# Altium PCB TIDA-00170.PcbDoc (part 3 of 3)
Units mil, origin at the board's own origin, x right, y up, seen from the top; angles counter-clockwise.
Board outline 3780 x 2000 mil, 4 copper layers (Top Layer, L2_GND-PLANE, L3_PWR-PLANE, Bottom Layer), stack 90 mil thick; 275 components, 132 nets, 768 pads, 262 vias.
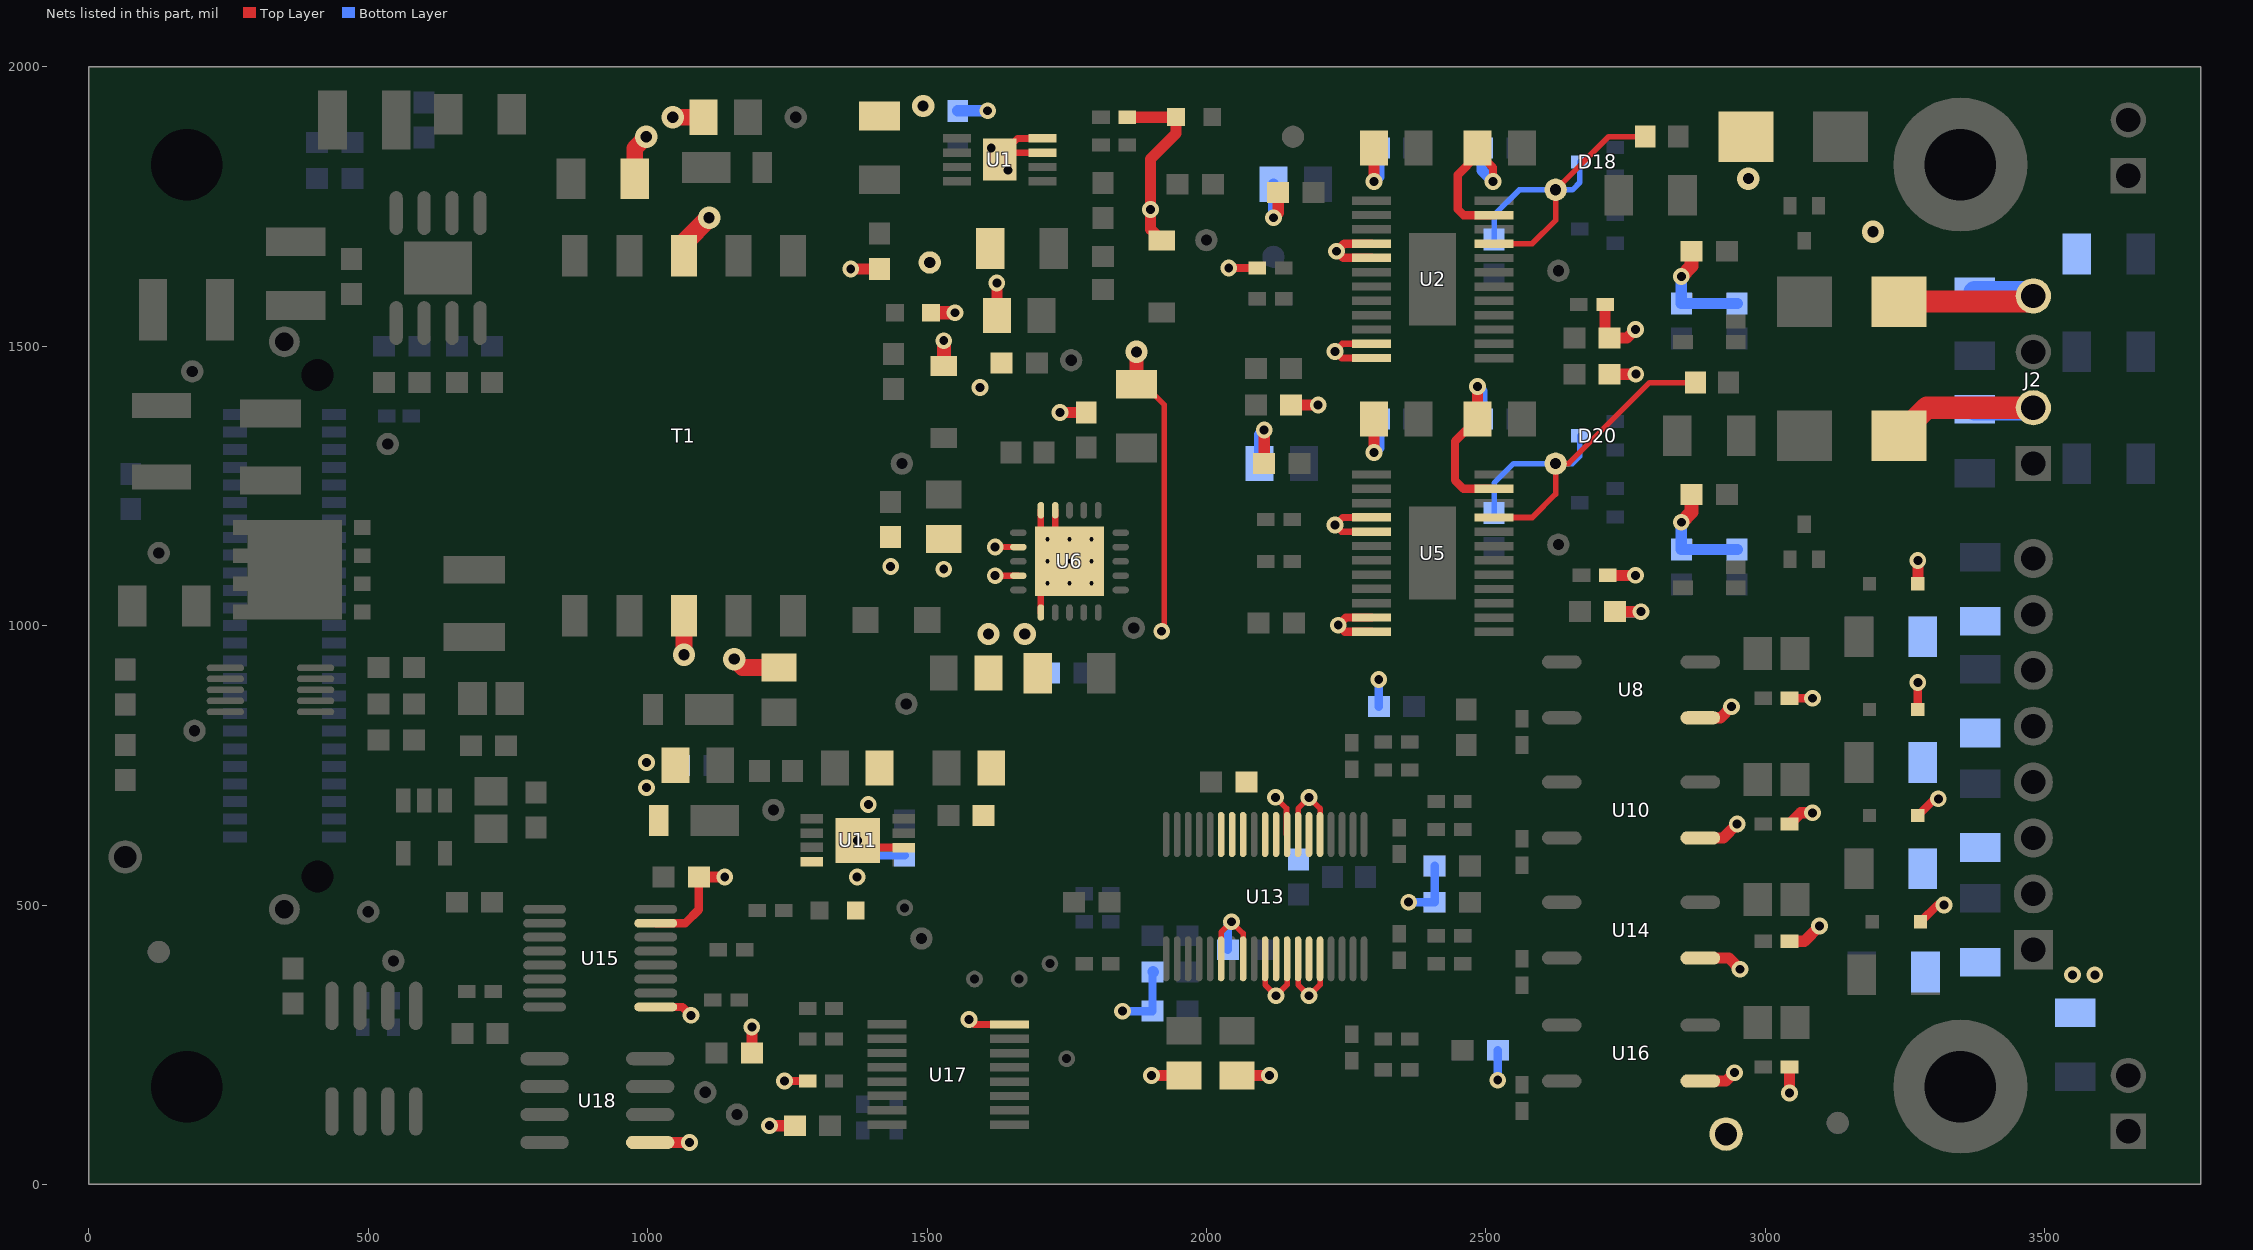
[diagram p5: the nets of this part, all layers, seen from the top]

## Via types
v1: diameter 30, hole 16, Top Layer to Bottom Layer, tented both sides, 197 vias
v2: diameter 40, hole 20, Top Layer to Bottom Layer, tented both sides, 46 vias
v3: diameter 20, hole 8, Top Layer to Bottom Layer, tented both sides, 9 vias
v4: diameter 24, hole 12, Top Layer to Bottom Layer, tented both sides, 6 vias
v5: diameter 25.98, hole 12, Top Layer to Bottom Layer, tented both sides, 4 vias

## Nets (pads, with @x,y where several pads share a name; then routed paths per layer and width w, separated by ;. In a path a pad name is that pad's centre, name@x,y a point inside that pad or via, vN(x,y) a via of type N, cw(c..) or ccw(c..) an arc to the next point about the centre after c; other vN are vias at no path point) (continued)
SGND: C3.1 C4.2 C5.2 C6.1 C7.2 C9.1 C11.1 C12.2 C14.2 C16.1 C17.1 C18.1 C19.2 C23.1 C24.2 C25.1 C27.1 C28.2 C29.2 C30.1 C32.1 C33.2 C34.2 C35.2 C37.2 C41.2 C42.2 C43.2 C44.2 C47.1 C48.1 C49.2 C51.2 C54.2 C56.2 C57.1 C60.2 C61.2 C62.1 C63.2 C64.2 C65.1 C66.1 C67.1 C68.2 C69.2 C70.2 C74.2 C75.2 C76.1 C78.2 C80.1 C81.1 C82.2 C83.2 C84.2 C85.2 C86.2 C87.2 C88.2 C89.2 C90.2 C91.2 C92.2 C93.1 C94.1 C95.2 D1.2 D2.1 D4.1 D6.1 D7.2 D8.2 D9.2 D11.2 D14.2 D15.2 D16.1 D17.2 D23.2 J2.2 J2.4 R1.2 R6.2 R8.2 R11.2 R12.1 R15.2 R18.2 R55.1 R63.1 R64.1 R68.1 R70.1 R75.2 T1.3 T1.8 TP4.1 TP28.1 U1.3 U1.4 U1.9 U2.4 U2.5 U2.11 U2.12 U2.23 U5.4 U5.5 U5.11 U5.12 U5.23 U6.4 U6.5 U6.7 U6.9 U6.11 U6.21 U8.3 U10.3 U11.4 U11.6 U11.9 U13.6 U13.8 U13.10 U13.11 U13.12 U13.13 U13.14 U13.15 U13.24 U13.25 U13.26 U13.27 U13.28 U13.29 U13.31 U13.32 U13.33 U14.3 U15.9 U15.15 U16.3 U17.8 U18.5 | length 7778.8
  Top Layer w10: C19.2@1875,1432.09 1887.91,1432.09 1924.42,1395.58 1924.42,994.42 v1(1920,990) ; U13.6@2026.26,403.78 2026.26,451.26 v1(2045,470) 2065.63,449.37 U13.8@2065.63,403.78 ; U13.10@2105,403.78 2105,357.24 v1(2124.68,337.56) 2144.37,357.24 U13.12@2144.37,403.78 ; v1(2123.74,692.66) 2143.43,672.98 U13.27@2143.43,626.44 ; U13.13@2164.06,403.78 2164.06,357.24 v1(2183.74,337.56) 2203.43,357.24 U13.15@2203.43,403.78 ; U13.26@2164.06,626.22 2164.06,672.76 v1(2183.74,692.44) 2203.43,672.76 U13.24@2203.43,626.22
  Top Layer w11: v1(1622,1089.41) U6.9@1663.46,1089.41 ; v1(1622,1140.59) U6.7@1663.46,1140.59
  Top Layer w12: U1.9@1630,1834 U1.9@1642.4,1846.4 ; U6.11@1703.82,1023.46 U6.21@1703.82,1083.23 ; U6.21@1703.82,1166.18 U6.5@1703.82,1206.54 ; U1.3@1707,1846.4 1636.4,1846.4 1662,1872 U1.4@1707,1872 ; U6.21@1715.63,1140.59 1729.41,1140.59 U6.4@1729.41,1206.54 ; U5.5@2295.7,1168.1 2241.9,1168.1 v1(2230,1180) 2243.7,1193.7 U5.4@2295.7,1193.7 ; U2.12@2295.7,1478.9 2241.9,1478.9 v1(2230,1490.8) 2243.7,1504.5 U2.11@2295.7,1504.5
  Top Layer w13: v1(1575,295) 1583.8,286.2 U17.8@1647.3,286.2
  Top Layer w15: U15.9@1014.41,317.5 1062.5,317.5 v1(1077.5,302.5) ; U15.15@1014.41,467.5 1067.5,467.5 1091.5,491.5 C51.2@1091.5,550 ; v1(1245,185) R55.1@1286.38,185 ; v1(1375.8,615.6) 1388.5,602.9 U11.6@1458.5,602.9 ; v1(2040,1640) R6.2@2091.38,1640 ; U5.12@2295.7,988.9 2247.9,988.9 v1(2236,1000.8) 2249.7,1014.5 U5.11@2295.7,1014.5 ; U2.5@2295.7,1658.1 2244.9,1658.1 v1(2233,1670) 2246.7,1683.7 U2.4@2295.7,1683.7 ; C6.1@2482.5,1857.5 C6.1@2485,1860 ; C24.2@2485,1370 2445,1330 2445,1260 2460.2,1244.8 U5.23@2514.7,1244.8 ; C6.1@2485,1855 C6.1@2485,1848 ; v1(2513,1795) 2513,1820 C6.1@2485,1848 ; U2.23@2514.7,1734.8 2460.2,1734.8 2450,1745 2450,1807 2485,1842 C6.1@2485,1848 ; C37.2@3043.62,870 v1(3085,870) ; D15.2@3273.31,660 3303.31,690 v1(3310,690) ; D14.2@3273.31,850 v1(3273.31,898.31) ; D17.2@3278.31,470 3308.31,500 v1(3320,500)
  Top Layer w20: U18.5@1004.49,75 v1(1075,75) ; C51.2@1091.5,550 v1(1137.99,550) ; C60.2@1186.5,235 v1(1186.5,281.5) ; v1(1218,105) C62.1@1263.5,105 ; v1(1363.5,1638.5) C11.1@1415,1638.5 ; C16.1@1625,1555 v1(1625,1613) ; v1(1738,1381.5) C25.1@1785,1381.5 ; R1.2@1858.62,1910 D1.2@1945.52,1910 1945.52,1880.52 1900,1835 v1(1900,1745) 1900,1709.47 D4.1@1920,1689.47 ; v1(1902,195) C56.2@1960,195 ; C57.1@2055,195 v1(2113,195) ; C27.1@2103.5,1290 v1(2103.5,1350) ; v1(2120,1730) 2128.5,1738.5 C9.1@2128.5,1775 ; R12.1@2151.5,1395 v1(2200,1395) ; v1(2300,1310) C23.1@2300,1370 ; v1(2300,1795) C5.2@2300,1855 ; C24.2@2485,1370 v1(2485,1428) ; R8.2@2713.62,1575 2713.62,1522.87 C17.1@2721.5,1515 2753,1515 v1(2768,1530) ; R15.2@2718.62,1090 v1(2768,1090) ; R11.2@2721.5,1450 v1(2768.5,1450) ; C32.1@2731.5,1025 v1(2778,1025) ; U16.3@2884.02,185 2930,185 v1(2945,200) ; U14.3@2884.02,405 2935,405 v1(2955,385) ; U10.3@2884.02,620 2925,620 v1(2950,645) ; U8.3@2884.02,835 2920,835 v1(2940,855) ; v1(3043.62,163.62) C61.2@3043.62,210 ; C54.2@3043.62,435 3070,435 v1(3097.47,462.47) ; C49.2@3043.62,645 3063.62,665 v1(3085,665) ; D11.2@3273.31,1075 v1(3273.31,1116.69)
  Top Layer w25: D6.1@1507.48,1560 v1(1550,1560) ; D8.2@1530,1464.47 v1(1530,1510) ; C19.2@1875,1432.09 v2(1875,1490) ; v1(2850,1185) 2868.5,1203.5 C29.2@2868.5,1235 ; v1(2850,1625) 2868.5,1643.5 C14.2@2868.5,1675
  Top Layer w30: C7.2@977.09,1800 977.09,1854.59 v2(997.5,1875) ; v2(1045,1910) C3.1@1100,1910 ; v2(1065,948) T1.8@1065,1017.95 ; v2(1155,940) 1170,925 C34.2@1235,925
  Top Layer w35: T1.3@1065,1662.05 1065,1685 v2(1110,1730)
  Top Layer w40: D9.2@3239.65,1340 3289.65,1390 J2.2@3480,1390 ; D7.2@3239.65,1580 3470,1580 J2.4@3480,1590
  Bottom Layer w15: v1(1375.8,615.6) 1402.9,588.5 C86.2@1460,588.5 ; v1(1850,310) C94.1@1903.5,310 R75.2@1903.5,380 ; C91.2@2038.5,420 2038.5,463.5 v1(2045,470) ; C84.2@2308.5,855 v1(2308.5,903.5) ; v1(2362,505) C90.2@2408.5,505 C89.2@2408.5,570 ; v1(2521.5,186.5) C95.2@2521.5,240
  Bottom Layer w20: C63.2@1555,1921.5 v1(1608.5,1921.5) ; R75.2@1904.25,380.75 R75.2@1905,380 ; C78.2@2095,1290 2095,1341.5 v1(2103.5,1350) ; v1(2120,1730) C66.1@2120,1790 ; v1(2300,1310) 2308.5,1318.5 C75.2@2308.5,1370 ; v1(2300,1795) 2308.5,1803.5 C65.1@2308.5,1855 ; v1(2485,1428) 2493.5,1419.5 C76.1@2493.5,1370 ; C64.2@2493.5,1855 2493.5,1814.5 v1(2513,1795) ; R18.2@2731.5,1025 v1(2778,1025) ; v1(2850,1185) C81.1@2850,1136.5 C80.1@2950,1136.5 ; v1(2850,1625) C70.2@2850,1576.5 C69.2@2950,1576.5
  Bottom Layer w40: C74.2@3375,1387.09 3477.09,1387.09 J2.2@3480,1390 ; C68.2@3375,1597.09 3462.91,1597.09 J2.4@3477.91,1582.09
  other v1: 3550,375 3590,375 1375,550 1395,680 998,710 998,755 1530,1101 1435,1106 1595,1426 1645,1815 1615,1855
  other v2: 1610,985 1675,985 3193,1705 2970,1800 1493,1930
  other v3: 1715.63,1075.63 1755,1075.63 1794.37,1075.63 1715.63,1115 1755,1115 1794.37,1115 1715.63,1154.37 1755,1154.37 1794.37,1154.37
VOUT0_0: C10.1 D18.3 FB1.2 TP2.1 U2.21 | length 639.8
  Top Layer w10: U2.21@2514.7,1683.6 2583.2,1683.6 2625,1725.4 TP2.1@2625,1780 2720,1875 FB1.2@2785.47,1875
  Bottom Layer w10: C10.1@2515,1691.5 2515,1735 2560,1780 TP2.1@2625,1780 2655,1780 2668.5,1793.5 D18.3@2668.5,1830
VOUT1_1: C26.1 D20.3 FB2.2 TP9.1 U5.21 | length 756.3
  Top Layer w10: U5.21@2514.7,1193.6 2583.2,1193.6 2625,1235.4 TP9.1@2625,1290 2648.09,1290 2793.09,1435 FB2.2@2875.47,1435
  Bottom Layer w10: C26.1@2515,1201.5 2515,1255 2550,1290 TP9.1@2625,1290 2655,1290 2668.5,1303.5 D20.3@2668.5,1340
pads on no net: FID1.1 FID2.1 FID3.1 FID4.1 FID5.1 FID6.1 J5.8 J5.9 J5.13 J5.14 J5.15 J5.17 J5.18 J5.19 J5.20 J5.21 J5.22 J5.23 J5.24 J5.25 J5.27 J5.28 J5.29 J5.30 J5.31 J5.32 J5.33 J5.34 J5.43 J5.44 J5.45 J5.46 J5.47 J5.48 J5.49 J5.MH1 J5.MH2 J5.MH3 J5.MH4 MH1.1 MH2.1 U1.7 U2.20 U5.20 U6.2 U6.6 U6.8 U6.10 U6.12 U6.17 U6.18 U6.19 U11.2 U11.3 U12.3 U12.4 U13.35

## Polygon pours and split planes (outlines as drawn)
+15V_ISO on Top Layer "Top Layer-No Net 1" (hatched 90Degree grid 5 track 10, remove dead copper, pour order 65): 2810,1090 2860,1090 2875,1075 2875,1050 2885,1040 2890,1040 3030,1040 3035,1045 3075,1085 3075,1110 3075,1140 3080,1145 3085,1150 3110,1150 3115,1150 3125,1140 3130,1135 3130,1060 3130,1045 3090,1005 3080,995 2880,995 2835,995 2810,1020 2785,1045 2785,1070 2785,1080 2795,1090 2810,1090
GND_EARTH on Top Layer "Top Layer-No Net 1" (hatched 90Degree grid 5 track 10, remove dead copper, pour order 96): 3710,50 3725,65 3725,235 3715,245 3235,245 3225,235 3225,60 3235,50
SGND on Top Layer "Top Layer-No Net 1" (hatched 90Degree grid 5 track 10, remove dead copper, pour order 90): 1400,465 1360.67,465 1350,475.67 1350,535 1325,560 1270,560 1265,565 1265,575 1270,580 1330,580 1340,590 1340,655 1395,710 1395,770 1425,770 1425,710 1405,690 1405,470
+6V_ISO on Top Layer "Top Layer-No Net 1" (hatched 90Degree grid 5 track 10, remove dead copper, pour order 80): 1440,565 1530,565 1560,595 1560,1043 1548,1055 1485,1055 1470,1040 1470,945 1430,905 1430,820 1465,785 1465,730 1495,700 1495,675 1490,670 1440,670 1440,650 1530,650 1540,640 1540,600 1520,580 1440,580
+18V_ISO on Top Layer "Top Layer-No Net 1" (hatched 90Degree grid 5 track 10, remove dead copper, pour order 77): 1825,780 1845,800 1845,880 1895,930 1895,1060 1885,1070 1840,1070 1840,1050 1825,1035 1805,1035 1805,980 1790,965 1750,965 1740,955 1740,870 1725,855 1725,790 1735,780
NetC19_1 on Top Layer "Top Layer-No Net 1" (hatched 90Degree grid 5 track 10, remove dead copper, pour order 79): 1840,1160 1900,1160 1910,1170 1910,1325 1900,1335 1700,1335 1700,1275 1705,1270 1735,1270 1750,1255 1750,1200 1760,1200 1760,1230 1765,1235 1795,1235 1800,1230 1800,1200 1830,1200 1840,1190
SGND on Top Layer "Top Layer-No Net 1" (hatched 90Degree grid 5 track 10, remove dead copper, pour order 89): 1635,1415 1510,1415 1505,1420 1505,1595 1565,1655 1565,1700 1605,1740 1605,1885 1575,1915 1384,1915 1384,1955 1645,1955 1660,1940 1660,1650 1645,1635 1645,1425
-18V_ISO on Top Layer "Top Layer-No Net 1" (hatched 90Degree grid 5 track 10, remove dead copper, pour order 91): 1365,1685 1485,1685 1570,1770 1570,1797 1477,1797 1470,1804 1470,1840 1495,1865 1495,1877 1487,1877 1435,1825 1335,1825 1310,1850 1310,1940 1295,1955 1170,1955 1155,1940 1155,1880 1190,1845 1190,1765 1220,1735 1315,1735
SGND on Top Layer "Top Layer-No Net 1" (hatched 90Degree grid 5 track 10, remove dead copper, pour order 66): 1595,645 1665,645 1675,655 1675,830 1720,875 1720,970 1680,1010 1605,1010 1595,1000
GND on Top Layer "Top Layer-No Net 1" (hatched 90Degree grid 5 track 10, remove dead copper, pour order 63): 325,1600 420,1600 430,1590 430,1560 450,1540 460,1530 535,1455 535,1405 495,1365 405,1365 290,1365 285,1370 285,1415 285,1435 315,1465 320,1470 320,1505 320,1595 325,1600
+15V_ISO on Top Layer "Top Layer-No Net 1" (hatched 90Degree grid 5 track 10, remove dead copper, pour order 83): 1660,1360 1660,1265 1610,1215 1375,1215 1355,1235 1355,1360 1375,1380 1640,1380
+18V_ISO on Top Layer "Top Layer-No Net 1" (hatched 90Degree grid 5 track 10, remove dead copper, pour order 69): 1280,880 1315,915 1375,915 1385,905 1385,805 1380,800 1075,800 1065,810 1065,875 1070,880
9.3V_NON_ISO on Top Layer "Top Layer-No Net" (hatched 90Degree grid 5 track 8, remove dead copper, pour order 92): 880,1040 815,1040 780,1005 645,1005 625,985 625,670 635,660 660,660 670,670 670,730 700,760 700,910 715,925 760,925 835,1000 875,1000 880,1005
+3.3V_NON_ISO on Top Layer "Top Layer-No Net" (hatched 90Degree grid 5 track 8, remove dead copper, pour order 95): 660,610 700,650 830,650 840,640 840,540 835,535 775,535 765,545 765,580 755,590 690,590 675,575 620,575 615,580 615,605 620,610
GND on Top Layer "Top Layer-No Net" (hatched 90Degree grid 5 track 8, remove dead copper, pour order 94): 835,680 735,680 735,893.1 751.9,910 830,910 845,895 845,690
+24VDC_LIMIT on Top Layer "Top Layer-No Net 9" (hatched 90Degree grid 5 track 8, remove dead copper, pour order 100): 505,980 505,925 535,925 535,950 540,955 560,955 625,1020 625,1285 620,1290 70,1290 70,1240 475,1240 480,1235 480,1005
GND on Top Layer "Top Layer-No Net" (hatched 90Degree grid 5 track 8, remove dead copper, pour order 109): 30,725 126,725 135,716 140,711 140,666 140,468 188,420 198,410 318,410 328,410 333,405 333,344 320,331 264,275 150,275 70,275 30,315 20,325 20,670 20,715 30,725
NetQ1_5 on Top Layer "Top Layer-No Net 11" (solid, remove dead copper, pour order 104): 170,1070 170,1000 455,1000 455,1190 260,1190 260,1070
+24VDC on Top Layer "Top Layer-No Net 10" (solid, remove dead copper, pour order 103): 25,1200 25,900 85,900 85,1045 100,1045 100,1085 110,1095 200,1095 200,1200
GND on Top Layer "Top Layer-No Net 7" (hatched 90Degree grid 5 track 8, remove dead copper, pour order 98): 450,1670 450,1640 455,1635 495,1635 535,1595 700,1595 710,1605 710,1665 785,1740 785,1900 800,1915 860,1915 870,1925 870,1955 860,1965 705,1965 695,1955 695,1695 680,1680 460,1680
NetC21_2 on Top Layer "Top Layer-No Net" (hatched 90Degree grid 5 track 8, remove dead copper, pour order 99): 785,1400 780,1395 715,1395 710,1400 710,1480 695,1495 695,1555 700,1560 725,1560 735,1570 735,1660 775,1700 870,1700 875,1695 875,1635 860,1620 796.22,1620 785,1608.78
NetC1_2 on Top Layer "Bottom Layer-No Net 3" (hatched 90Degree grid 5 track 8, remove dead copper, pour order 102): 75,1370 75,1420 130,1420 210,1500 210,1840 470,1840 485,1855 485,1950 500,1965 650,1965 660,1955 660,1705 655,1700 635,1700 630,1705 630,1820 615,1835 575,1835 565,1825 565,1805 555,1795 505,1795 420,1710 420,1650 410,1640 320,1640 290,1610 290,1475 185,1370
SGND on Top Layer "Top Layer-No Net 1" (hatched 90Degree grid 5 track 10, remove dead copper, pour order 86): 1390,1170 1570,1170 1575,1165 1575,1095 1570,1090 1390,1090 1380,1100 1380,1160
-15V_ISO on Top Layer "Top Layer-No Net 1" (hatched 90Degree grid 5 track 10, remove dead copper, pour order 84): 1940,1605 1940,1535 1935,1530 1835,1530 1825,1520 1825,1440 1815,1430 1695,1430 1680,1445 1680,1600 1690,1610 1935,1610
NetC8_1 on Top Layer "Top Layer-No Net 1" (hatched 90Degree grid 5 track 10, remove dead copper, pour order 82): 1699.17,1800 1740,1800 1745,1795 1745,1770 1770,1745 1830,1745 1840,1735 1840,1650 1695,1650 1695,1795
SGND on Top Layer "Top Layer-No Net 1" (hatched 90Degree grid 5 track 10, remove dead copper, pour order 62): 2100,445 2100,285 2115,270 2120,265 2170,265 2190,265 2200,275 2205,280 2205,320 2205,445 2200,450 2115,450 2105,450 2100,445
SGND on Top Layer "Top Layer-No Net 1" (hatched 90Degree grid 5 track 10, remove dead copper, pour order 113): 2030,580 2030,665 2055,690 2055,750 2070,765 2190,765 2205,745 2206.11,593.11 2193,580
GND_EARTH on Top Layer "Top Layer-No Net 1" (hatched 90Degree grid 5 track 10, remove dead copper, pour order 97): 3710,1950 3725,1935 3725,1765 3715,1755 3250,1755 3170,1835 3095,1835 3095,1945 3100,1950
SGND on Top Layer "Top Layer-No Net 1" (hatched 90Degree grid 5 track 10, remove dead copper, pour order 114): 3015,1786 3015,1915 2969.92,1960.08 2923.08,1960.08 2912,1949 2912,1811 2938,1785 3014,1785
-15V_ISO on Top Layer "Top Layer-No Net 1" (hatched 90Degree grid 5 track 10, remove dead copper, pour order 118): 2450,920 2360,920 2360,1220 2450,1220
-15V_ISO on Top Layer "Top Layer-No Net 1" (hatched 90Degree grid 5 track 10, remove dead copper, pour order 117): 2450,1455 2360,1455 2360,1710 2450,1710
SGND on Top Layer "Top Layer-No Net 1" (hatched 90Degree grid 5 track 10, remove dead copper, pour order 93): 995,630 990,635 990,760 995,765 1065,765 1075,755 1075,730 1070,725 1050,725 1045,720 1045,635 1040,630
+5V_ISO on Top Layer "Top Layer-No Net 1" (hatched 90Degree grid 5 track 10, remove dead copper, pour order 88): 1207.68,775 1215,767.68 1215,705 1250,670 1250,630 1250,615 1240,605 1240,550 1235,545 1190,545 1145,590 1095,590 1080,605 1080,680 1105,705 1105,760 1120,775
SGND on Bottom Layer "Top Layer-No Net 1" (hatched 90Degree grid 5 track 10, remove dead copper, pour order 85): 3305,1095 3295,1055 3090,1055 3080,1065 3080,1620 3025,1675 3025,1755 2995,1785 2938,1785 2895,1828 2895,1920 2910,1935 2995,1935 3015,1915 3015,1845 3065,1795 3140,1795 3285,1650 3480,1650 3540,1710 3580,1710 3585,1705 3585,1585 3571,1571 3321,1571 3305,1555
+15V_ISO on Bottom Layer "Top Layer-No Net 1" (hatched 90Degree grid 5 track 10, remove dead copper, pour order 67): 2980,1695 2890,1695 2835,1750 2805,1780 2735,1780 2720,1780 2705,1795 2705,1820 2710,1825 2755,1825 2775,1845 2806.5,1845 2885,1766.5 2978.5,1766.5 2985,1760 2990,1755 2990,1745 2990,1700 2985,1695 2975,1695
-15V_ISO on Bottom Layer "Top Layer-No Net 1" (hatched 90Degree grid 5 track 10, remove dead copper, pour order 61): 2925,1090 2925,1045 2940,1030 3025,1030 3040,1045 3040,1530 3010,1560 2990,1560 2835,1405 2730,1405 2705,1380 2705,1355 2715,1345 2800,1345 2825,1320 2825,1285 2810,1270 2730,1270 2720,1260 2720,1225 2730,1215 2960,1215 2985,1190 2985,1110 2970,1095 2930,1095
SGND on Bottom Layer "Top Layer-No Net 1" (hatched 90Degree grid 5 track 10, remove dead copper, pour order 64): 3605,285 3498,285 3438,345 3283,345 3270,361 3270,410 3325,410 3355,440 3590,440 3615,415 3615,295
SGND on Bottom Layer "Top Layer-No Net 1" (hatched 90Degree grid 5 track 10, remove dead copper, pour order 74): 3255,1060 3400,1060 3425,1035 3425,975 3420,970 3340,970 3330,960 3330,885 3325,880 3255,880
SGND on Bottom Layer "Top Layer-No Net 1" (hatched 90Degree grid 5 track 10, remove dead copper, pour order 75): 3255,860 3400,860 3425,835 3425,775 3420,770 3340,770 3330,760 3330,685 3325,680 3255,680
SGND on Bottom Layer "Top Layer-No Net 1" (hatched 90Degree grid 5 track 10, remove dead copper, pour order 76): 3255,660 3400,660 3425,635 3425,575 3420,570 3340,570 3330,560 3330,485 3325,480 3255,480
9.3V_NON_ISO on Bottom Layer "Top Layer-No Net" (hatched 90Degree grid 5 track 8, remove dead copper, pour order 105): 680,800 620,800 605,815 605,1020 585,1040 585,1215 495,1305 495,1370 505,1380 540,1380 545,1375 545,1340 645,1240 645,1035 690,990 690,810
GND on Bottom Layer "Top Layer-No Net" (hatched 90Degree grid 5 track 8, remove dead copper, pour order 108): 820,45 102.76,45 35,112.76 35,735 45,745 150,745 240,835 240,1100 255,1115 480,1115 503.81,1190 520,1225 220,1225 170,1275 50,1275 25,1300 25,1735 250,1960 870,1960 880,1950 880,1665 850,1635 785,1635 775,1625 775,1610 715,1550 610,1550 585,1575 470,1575 445,1550 445,1490 470,1465 470.08,1255 470,1240 470.08,1225 555,1225 570,1210 570,780 585,765 695,765 725,795 725,1025 675,1075 675,1245 685,1255 685,1350 710,1375 765,1375 785,1355 785,1055 800,1040 870,1040 885,1025 885,990 875,980 840,980 830,970 830,55
+24VDC on Bottom Layer "Bottom Layer-No Net 2" (solid, remove dead copper, pour order 101): 465,1195 470,1190 470,1150 465,1145 215,1145 195,1125 195,915 180,900 40,900 25,915 25,1220 35,1230 110,1230 145,1195
SGND on Bottom Layer "Top Layer-No Net 1" (hatched 90Degree grid 5 track 10, remove dead copper, pour order 71): 3205,915 3195,925 3080,925 3055,950 2740,950 2730,940 2730,830.83 2735,825 3190,825 3205,842.5
SGND on Bottom Layer "Top Layer-No Net 1" (hatched 90Degree grid 5 track 10, remove dead copper, pour order 78): 3060,400 3070,390 3070,100 3015,45 1540,45 1530,55 1530,160 1540,170 1630,170 1810,350 2090,350 2125,385 2230,385 2245,370 2245,200 2295,150 2555,150 2590,185 2590,375 2615,400
SGND on Bottom Layer "Top Layer-No Net 1" (hatched 90Degree grid 5 track 10, remove dead copper, pour order 68): 2200,585 2095,585 2090,590 2090,715 2105,730 2170,730 2205,695 2205,590
-15V_ISO on Bottom Layer "Top Layer-No Net 1" (hatched 90Degree grid 5 track 10, remove dead copper, pour order 115): 2325,185 2295,185 2285,195 2285,405 2320,440 2320,635 2220,735 2220,946 2315,1041 2315,1221 2355,1261 2355,1880 2365,1890 2445,1890 2455,1880 2455,942 2438,925 2290,925 2271,906 2271,827 2283,815 2320,815 2330,805 2330,700 2360,670 2415,670 2420,665 2420,617 2413,610 2375,610 2335,570 2335,485 2353,467 2409,467 2420,456 2420,415 2416,411 2361,411 2330,380 2330,190
SGND on Bottom Layer "Top Layer-No Net 1" (hatched 90Degree grid 5 track 10, remove dead copper, pour order 73): 3120,455 2995,580 2665,580 2605,520 2605,470 2630,445 3110,445
SGND on Bottom Layer "Top Layer-No Net 1" (hatched 90Degree grid 5 track 10, remove dead copper, pour order 72): 3100,700 3020,780 2650,780 2565,695 2565,650 2585,630 3085,630 3100,645
GND_EARTH on Bottom Layer "Top Layer-No Net 1" (hatched 90Degree grid 5 track 10, remove dead copper, pour order 87): 3660,1726.02 3631.02,1755 3423,1755 3395,1720 3300,1720 3210,1810 3210,1925 3235,1950 3710,1950 3740,1920 3740,85 3710,55 3225,55 3215,65 3215,225 3280,290 3410,290 3485,215 3615,215 3660,260
SGND on Bottom Layer "Top Layer-No Net 1" (hatched 90Degree grid 5 track 10, remove dead copper, pour order 81): 1065,815 1085,835 1250,835 1350,735 1350,490 1360,480 1505,480 1735,710 1735,1045 1750,1060 1830,1060 1840,1050 1840,945 1870,915 1955,915 1970,930 1970,1890 1895,1965 985,1965 960,1940 960,1650 975,1635 1325,1635 1340,1620 1340,1055 1325,1040 965,1040 955,1030 955,995 960,990 985,990 995,980 994,56 1010,40 1285,40 1300,55 1300,390 1285,405 1090,405 1065,430
+5V_ISO on Bottom Layer "Top Layer-No Net 1" (hatched 90Degree grid 5 track 10, remove dead copper, pour order 121): 1110,775 1110,630 1195,545 1245,545 1260,560 1260,765 1245,780 1115,780
+3.3V_NON_ISO on L3_PWR-PLANE "Top Layer-No Net" (hatched 90Degree grid 5 track 8, remove dead copper, pour order 106): 830,665 845,650 845,45 830,30 410,30 365,75 365,320 330,355 95,355 35,415 35,810 60,835 395,835 565,665
+5V_ISO on L3_PWR-PLANE "Top Layer-No Net 1" (hatched 90Degree grid 5 track 10, remove dead copper, pour order 111): 1000,715 990,705 990,75 1025,40 2865,40 2885,60 2885,860 2880,865 2295,865 2275,885 2275,1715 2215,1775 2020,1775 1935,1690 1935,865 1785,715
+18V_ISO on L3_PWR-PLANE "Top Layer-No Net 1" (hatched 90Degree grid 5 track 10, remove dead copper, pour order 60): 1825,810 1795,780 1320,780 1285,815 1285,895 1315,925 1800,925 1825,900
SGND on L3_PWR-PLANE "Top Layer-No Net 1" (hatched 90Degree grid 5 track 10, remove dead copper, pour order 116): 1860,1125 1860,1385 1840,1405 1675,1405 1660,1420 1660,1630 1640,1650 1595,1650 1525,1580 1525,1230 1500,1205 1375,1205 1350,1180 1350,1055 1325,1030 1020,1030 1000,1010 1000,805 1035,770 1195,770 1215,790 1215,885 1290,960 1820,960 1830,975 1830,1095
-15V_ISO on L3_PWR-PLANE "Top Layer-No Net 1" (hatched 90Degree grid 5 track 10, remove dead copper, pour order 112): 1910,1460 1880,1430 1735,1430 1700,1465 1700,1750 1810,1860 2440,1860 2465,1835 2465,1510 2505,1470 2505,1005 2550,960 2855,960 2895,1000 2895,1560 2755,1700 2755,1755 2770,1770 2850,1770 2860,1780 2860,1850 2825,1885 2730,1885 2715,1900 2715,1955 2725,1965 2975,1965 3020,1920 3020,1835 3045,1810 3120,1810 3315,1615 3315,995 3220,900 2360,900 2330,930 2330,1690 2220,1800 2000,1800 1910,1710
+15V_ISO on L3_PWR-PLANE "Top Layer-No Net 1" (hatched 90Degree grid 5 track 10, remove dead copper, pour order 110): 2685,1865 2710,1840 2800,1840 2810,1830 2810,1810 2805,1805 2740,1805 2730,1795 2730,1670 2865,1535 2865,1015 2845,995 2570,995 2545,1020 2545,1500 2495,1550 2495,1845 2445,1895 1790,1895 1490,1595 1490,1260 1475,1245 1370,1245 1345,1270 1345,1920 1390,1965 2680,1965 2685,1960
GND on L2_GND-PLANE "Top Layer-No Net" (hatched 90Degree grid 5 track 8, remove dead copper, pour order 107): 835,35 99.13,35 32,102.14 30,104.13 30,465 30,1930 65,1965 125,1965 388,1965 860,1965 874,1951 885,1940 885,1875 885,1650 870,1635 810,1635 795,1635 780,1620 780,1600 780,1055 795,1040 853,1040 871,1040 880,1031 880,985 875,980 855,980 850,980 840,970 840,930 840,40 835,35
SGND on L2_GND-PLANE "Top Layer-No Net 1" (hatched 90Degree grid 5 track 10, remove dead copper, pour order 70): 1005,45 2990,45 3070,125 3070,185 3230,345 3438,345 3498,285 3605,285 3615,295 3615,415 3590,440 3585,1705 3580,1710 3540,1710 3480,1650 3280,1650 3120,1810 3045,1810 3020,1835 3020,1920 2975,1965 985,1965 955,1935 954.76,1662.83 982.32,1635.28 1320,1635 1335,1620 1335,1060 1320,1045 955,1045 955,985 990,985 990,60

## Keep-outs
Keep-Out Layer:
  circle w4: c409.06,551.18 r32
  circle w4: c409.06,1448.82 r35
  lines w10: -5,0 ccw(c0,0) 0,-5 ; -5,0 ccw(c0,0) 0,-5 ; -5,0 ccw(c0,0) 0,-5 ; -5,0 ccw(c0,0) 0,-5 ; -5,0 ccw(c0,0) 0,-5 ; -5,0 ccw(c0,0) 0,-5
  text ".Layer_Name" at 577,-858.49 h60

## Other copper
Top Layer:
  pour cut-out: 513,1187 513,1155.14 505.86,1148 476,1148 472,1152 472,1178 481,1187
  region net SCLK_ISO: 1947.52,1100 1955,1092.52 1955,1087.48 1947.52,1080
  text ".Layer_Name" at 577,-858.49 h60
L2_GND-PLANE:
  pour cut-out: 2390,270 2390,210 2421.5,210 2425,206.5 2425,265 2420,270
  text ".Layer_Name" at 612,-866 h60
L3_PWR-PLANE:
  text ".Layer_Name" at 640,-860 h60
Bottom Layer:
  pour cut-out: 1518,1890 1518,1815 1528,1805 1583,1805 1593,1815 1593,1884.89 1582.89,1895 1523,1895
  pour cut-out: 1420,691 1420,611 1431,600 1473,600 1495,578 1495,576 1530,576 1543,589 1543,663 1506,700 1429,700
  pour cut-out: 505,1220 470,1220 470,1270 500,1270 510,1260 510,1225
  pour cut-out: 505,1750 505,1845 500,1850 385,1850 378,1843 378,1750.07 383.07,1745 500,1745
  pour cut-out: 592,1834 481,1834 479,1836 479,1966 489,1976 573,1976 574,1975 574,1889 592,1871
  pour cut-out: 327.83,600.2 227.8,600.2 223,605 223,673 235,685 345,685 360,670 360,632.37
  pour cut-out: 530,295 505,295 505,400 530,400 530,390 535,385 535,300
  pour cut-out: 508.88,240.88 471.65,242 466.19,247.46 466.19,403.84 470.35,408 535,408 541,402 541,273
  pour cut-out: 568.81,381.19 560,390 530,390 530,300 532.5,297.5 535.87,300.87 568.81,300.87
  pour cut-out: 2115,395 2115,332 2053,270 1933,270 1923,280 1923,353 1930,360 2040,360 2075,395
  pour cut-out: 1945,365 1950,360 1950,340 1945,335 1780,335 1770,345 1770,360 1775,365
  pour cut-out: 383.83,605 357.33,578.5 357.33,531 385.21,503.12 437.12,503.12 460,526 460,596 451,605
  text "ISE-PLC-AIM-300" at 2530,1915 h40
  text ".Layer_Name" at 577,-858.49 h60
Multi-Layer:
  pour cut-out: 851.18,0 978.35,0 978.35,975 940,975 940,1055 1323.78,1055 1323.78,1620 945,1620 945,2000 890,2000 890,1620 796.22,1620 796.22,1055 895,1055 895,970 851.18,970

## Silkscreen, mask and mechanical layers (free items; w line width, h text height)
Top Overlay:
  circle w25: c535,1024 r6
  circle w11: c669,685 r5
  circle w20: c394,125 r6
  circle w10: c2988.94,1067.6 r9.06
  circle w10: c2988.94,1507.6 r9.06
  circle w10: c3485.03,327 r18.97
  lines w6: 1250,646 1255,641 1255,550 ; 1305,542.4 1440,542.4 ; 1305,689.2 1440,689.2 ; 1376,1232 1425,1281 ; 1382.6,77.1 1699.66,77.1 ; 1382.6,77.17 1382.6,315.3 ; 1382.6,315.4 1699.9,315.4 ; 1512,1815 1512,1760.2 1747,1760.2 1747,1905.2 1512,1905.2 1512,1860 ; 1699.84,77.28 1699.84,315.34 ; 2499.98,477.73 2517.72,460 ; 3135,1475 3150,1475 ; 3148,1782 3163,1782 ; 3160,1460 3160,1490 ; 3170,1475 3185,1475 ; 3173,1767 3173,1797 ; 3183,1782 3198,1782 ; 3160,1475 3150,1465 3150,1485 3160,1475 ; 3160,1475 3170,1465 3170,1485 3160,1475 ; 3173,1782 3183,1792 3183,1772 3173,1782 ; 3173,1782 3163,1792 3163,1772 3173,1782 ; 2245,959.9 2565,959.9 2565,1299.9 2245,1299.9 2245,959.9 ; 2245,1449.9 2565,1449.9 2565,1789.9 2245,1789.9 2245,1449.9
  text "TIDA-00170" at 2145,120 h40
  text "ISE-PLC-AIM-300" at 1785,60 h40
  text "Rev E1" at 2325,60 h40
  text ".Layer_Name" at 577,-858.49 h60
Bottom Overlay:
  circle w10: c207,622 r7.62
  lines w6: 565,1639 565,1574 559,1580 572,1580 566,1574
  text "49" at 218,1360 h50
  text "2" at 506,604 h50
  text "TIDA-00170" at 3028,470 h35
  text "ISE-PLC-AIM-300" at 3053,320 h35
  text ".Layer_Name" at 577,-858.49 h60
Top Paste:
  text ".Layer_Name" at 577,-858.49 h60
Bottom Paste:
  text ".Layer_Name" at 577,-858.49 h60
Top Solder:
  text ".Layer_Name" at 577,-858.49 h60
  text ".Layer_Name" at 577,-858.49 h60
Bottom Solder:
  text ".Layer_Name" at 577,-858.49 h60
Drill Guide:
  text ".Layer_Name" at 577,-858.49 h60
M1 Board Outline:
  the board outline again, w10
M2 Board Dimensions:
  rectangle: -0.5,-285.5 124.5,-160.5
  rectangle: 124.5,-410.5 499.5,-285.5
  lines w7: -0.5,-285.5 999.5,-285.5 ; 124.5,-410.5 124.5,-160.5 ; 249.5,-410.5 249.5,-160.5 ; 499.5,-410.5 499.5,-160.5 ; 749.5,-410.5 749.5,-160.5 ; -0.5,-410.5 999.5,-410.5 999.5,-160.5 -0.5,-160.5 -0.5,-410.5
  lines w7.87: 0,25 3780,25 ; 0,1960 3780,1960 ; 50,45 50,2000 ; 1645,1420 1830,1420 1870,1460 1870,1680 2010,1820 2345,1820 2370,1795 2370,960 2415,915 2655,915 2700,870 2700,225 2715,210 2760,210 2775,225 2775,925 2820,970 2880,1030 3045,1030 3150,1030 3245,1125 3475,1125 3490,1110 3745,1110 ; 2615,1230 2710,1230 2725,1245 2725,1805 2745,1825 2805,1825 2825,1805 2825,1130 2845,1110 2908.83,1110 2920,1121.17 2920,1160 ; 2685,1230 2520,1230 2500,1250 2500,1860 2480,1880 1595,1880 1575,1860 1575,1570 1645,1500 1645,1265 1625,1245 1465,1245 1450,1260 1450,1920 1490,1960 3110,1960 3110,1245 3090,1225 3045,1225 3035,1235 3035,1858.07 3013.07,1880 2940,1880 2920,1860 2920,1135 ; 3745,0 3745,2000
  lines w10: -0.5,-475.5 -0.5,-455.5 ; 59.5,-485.5 -0.5,-465.5 ; 59.5,-445.5 -0.5,-465.5 ; 223.58,-465.5 -0.5,-465.5 ; 775.42,-465.5 999.5,-465.5 ; 939.5,-485.5 999.5,-465.5 ; 939.5,-445.5 999.5,-465.5 ; 999.5,-475.5 999.5,-455.5
  text "1000 (mil)" at 233.58,-501.49 h60
  text ".Layer_Name" at 577,-858.49 h60
M3 3D STEP Top:
  text ".Layer_Name" at 577,-858.49 h60
M4 3D STEP Bottom:
  text ".Layer_Name" at 577,-858.49 h60
M5 Assembly Top:
  circle w15: c638,727 r6
  circle w15: c244.29,951.93 r6
  lines w3.94: 293.5,822.01 293.5,947.99 356.5,947.99 356.5,822.01 293.5,822.01
  lines w6: 1198.5,712.32 1261.5,712.32 ; 1198.5,767.68 1261.5,767.68 ; 1305,435 1330,435 ; 1328.58,474.25 1351.42,474.25 ; 1328.58,505.75 1351.42,505.75 ; 1355,410 1355,460 ; 1380,435 1355,435 ; 1440.5,1602 1465.5,1602 ; 1485,1584 1485,1624 ; 1509,1603 1484,1603 ; 1648.5,1282.32 1711.5,1282.32 ; 1648.5,1337.68 1711.5,1337.68 ; 1787.32,1599.5 1787.32,1662.5 ; 1842.68,1599.5 1842.68,1662.5 ; 1966.58,1894.25 1989.42,1894.25 ; 1966.58,1925.75 1989.42,1925.75 ; 2034.79,1910.04 2059.79,1910.04 ; 2083,1911.83 2059.79,1935.04 2059.79,1885.04 2084.79,1910.04 ; 2084.79,1885.04 2084.79,1935.04 ; 2088,1910.04 2109.79,1910.04 ; 2960.04,1797.44 3139.97,1797.44 ; 2960.04,1952.56 3139.97,1952.56 ; 3065.04,1262.44 3244.97,1262.44 ; 3065.04,1417.56 3244.97,1417.56 ; 3065.04,1502.44 3244.97,1502.44 ; 3065.04,1657.56 3244.97,1657.56 ; 3135,1230 3150,1230 ; 3135,1475 3150,1475 ; 3148,1782 3163,1782 ; 3160,1215 3160,1245 ; 3160,1460 3160,1490 ; 3170,1230 3185,1230 ; 3170,1475 3185,1475 ; 3173,1767 3173,1797 ; 3183,1782 3198,1782 ; 1355,435 1330,410 1330,460 1355,435 ; 1484,1603 1465.5,1621.5 1465.5,1587.5 1467,1586 1484,1603 ; 3160,1230 3170,1220 3170,1240 3160,1230 ; 3160,1230 3150,1220 3150,1240 3160,1230 ; 3160,1475 3150,1485 3150,1465 3160,1475 ; 3160,1475 3170,1485 3170,1465 3160,1475 ; 3173,1782 3183,1772 3183,1792 3173,1782 ; 3173,1782 3163,1772 3163,1792 3173,1782
  lines w10: -292,-930.17 6308,-930.17 ; -292,-726.83 6310,-726.83 ; -292,-523.5 -292,-1133.5 3713,-1133.5 6310,-1133.5 6310,-523.5 -291.5,-523.5 -291.5,-1133.5 1284,-1133.5 ; 2173,-1133.5 2173,-523.5 ; 3735,-726 3735,-522.67 ; 4280,-726.83 4280,-523.5 ; 4902,-1140 4902,-937.17
  text "D1" at 1962,1938 h30
  text "D2" at 3009.82,1851.59 h50
  text "L1" at 1830,1611 h30 r90
  text "D7" at 3119.01,1553.85 h50
  text "J2" at 3628.07,1414.13 h50
  text "D9" at 3114.59,1315.96 h50
  text "L3" at 1657,1295 h30
  text "L4" at 1203.39,724.14 h35
  text "D16" at 1361.46,475.53 h30
  text "COMPONENTS MARKED 'DNP' SHOULD NOT BE POPULATED." at 1153.5,-318.5 h60
  text "ASSEMBLY VARIANT:" at 1153,-434 h60
  text ".VariantName" at 2189,-434 h60
  text "PCB VIEWED FROM TOP SIDE" at -228.5,-655.67 h60
  text "BOARD #:" at 2248,-655.67 h60
  text "ISE-PLC-AIM-300" at 2793.5,-655.67 h60
  text "SVN REV:" at 4476,-655.67 h60
  text ".VersionControl_RevNumber" at 4982,-655.67 h60
  text "REV: E1" at 3805,-660 h60
  text "IGNORE ->" at -228.5,-858.49 h60
  text "PLOT NAME =" at -228.5,-1064.34 h60
  text ".plot_File_Name" at 577,-1064.34 h60
  text "GENERATED    :" at 2250,-1064.34 h60
  text ".Print_Date" at 3119.5,-1064.34 h60
  text ".Print_Time" at 3848.5,-1064.34 h60
  text "TEXAS INSTRUMENTS" at 5113,-1064.34 h60
M6 Assembly Bottom:
  circle w20: c212,618 r6
  lines w10: -292.5,-727.33 6309.5,-727.33 ; -290.5,-930.67 6309.5,-930.67 ; 1115.5,-1140.5 1115.5,-937.67 ; 1737.5,-727.33 1737.5,-524 ; 2236,-723 2236,-519.67 ; 3844.5,-1134 3844.5,-524 ; 4733.5,-1134 6309,-1134 6309,-524 -292.5,-524 -292.5,-1134 2304.5,-1134 6309.5,-1134 6309.5,-524
  text "49" at 222,1358 h40
  text "2" at 501,596 h40
  text "COMPONENTS MARKED 'DNP' SHOULD NOT BE POPULATED." at 6102,-318 h60
  text ".VariantName" at 5058,-434 h60
  text "ASSEMBLY VARIANT:" at 6097,-434 h60
  text "REV: E1" at 2173,-655 h60
  text ".VersionControl_RevNumber" at 1035.5,-656.17 h60
  text "SVN REV:" at 1541.5,-656.17 h60
  text "ISE-PLC-AIM-300" at 3224,-656.17 h60
  text "BOARD #:" at 3769.5,-656.17 h60
  text "PCB VIEWED FROM BOTTOM SIDE" at 6246,-656.17 h60
  text "IGNORE ->" at 2547.85,-858.49 h60
  text "TEXAS INSTRUMENTS" at 904.5,-1064.84 h60
  text ".Print_Time" at 2169,-1064.84 h60
  text ".Print_Date" at 2898,-1064.84 h60
  text "GENERATED    :" at 3767.5,-1064.84 h60
  text ".plot_File_Name" at 5440.5,-1064.84 h60
  text "PLOT NAME =" at 6246,-1064.84 h60
M9 Title Sheet:
  drawing of 57 lines, arcs and shapes, not listed
  text "1" at 739.84,8036.5 h70
  text "2" at 3235.5,8036.5 h70
  text "3" at 5724.84,8036.5 h70
  text "4" at 8231.51,8036.5 h70
  text "5" at 10730.5,8036.5 h70
  text "6" at 13235.5,8036.5 h70
  text "A" at -416.5,6893.5 h70
  text "A" at 14383.5,6893.5 h70
  text "B" at -416.5,4513.5 h70
  text "B" at 14383.5,4513.5 h70
  text "C" at -416.5,2138.5 h70
  text "C" at 14383.5,2138.5 h70
  text "PROJECT TITLE:" at 11343.5,277.5 h45
  text ".PRJ_Title" at 11393.5,144.17 h70
  text "DESIGNED FOR:" at 11343.5,-23.5 h45
  text ".PRJ_Customer" at 11393.5,-163.5 h70
  text "D" at -416.5,-231.5 h70
  text "D" at 14383.5,-231.5 h70
  text "FILE NAME:" at 11343.5,-323.5 h45
  text "ISE-PLC-AIM-300" at 11393.5,-443.5 h70
  text "Texas Instruments (TI) and/or its licensors do not warrant the accuracy or completeness of this specification" at 6374,-605.34 h45
  text "ENGINEER:" at 11343.5,-613.5 h45
  text "LAYOUT BY:" at 12848.5,-613.5 h45
  text "or any information contained therein. TI and/or its licensors do not warrant that this design will meet" at 6329.01,-718 h45
  text ".PRJ_Engineer" at 11393.5,-768.49 h70
  text "the specifications, will be suitable for your application or fit for any particular purpose, or will operate in" at 6329.01,-830.67 h45
  text "ALTIUM DESIGNER VERSION:" at 12848.5,-923.5 h45
  text "an implementation. TI and/or its licensors do not warrant that the design is production worthy. You should" at 6329.01,-943.33 h45
  text "completely validate and test your design implementation to confirm the system functionality for your application." at 6374,-1056 h45
  text ".print_Scale" at 11393.5,-1056.83 h70
  text ".Application_BuildNumber" at 12899,-1056.83 h70
  text "1" at 739.84,-1263.5 h70
  text "2" at 3235.5,-1263.5 h70
  text "3" at 5724.84,-1263.5 h70
  text "4" at 8231.51,-1263.5 h70
  text "5" at 10730.5,-1263.5 h70
  text "6" at 13235.5,-1263.5 h70
M10 Fab Notes:
  drawing of 220 lines, arcs and shapes, not listed
  text "DESIGN INFORMATION" at 12381.02,6810 h60
  text "(REFER ALSO ARRAY/PANEL PROFILING INFORMATION)" at 12019.46,6648.29 h60
  text "BOARD SIZE" at 11333.46,6644 h60
  text "3780MIL" at 11795.78,6516.18 h60
  text "X" at 12301.46,6516.18 h60
  text "2000MIL" at 12532.78,6516.18 h60
  text "Number of Layers :" at 11736.46,6319 h60
  text "4" at 12831.27,6309 h60
  text "MIN. TRACK WIDTH:" at 11736.46,6180 h60
  text "8" at 12832.7,6180 h60
  text "MIL" at 12987.46,6180 h60
  text "7.87" at 12737,6051 h60
  text "MIN. CLEARANCE:" at 11736.46,6048 h60
  text "MIL" at 12987.46,6048 h60
  text "MIN. VIA PAD SIZE:" at 11736.46,5916 h60
  text "24" at 12802.71,5916 h60
  text "MIL" at 12987.46,5916 h60
  text "0.152mm (6MIL)" at 12431.46,5774.29 h60
  text "EXTERNAL" at 13182,5772 h60
  text "MINIMUM ANNULAR RING" at 11407.23,5770 h60
  text "PER" at 11607.23,5652 h60
  text "IPC-D-275 CLASS 2 LEVEL C" at 11827.23,5652 h60
  text "MIL, HOLES" at 13315.46,5539.71 h60
  text "+/-" at 12923,5539 h60
  text "+/-" at 13777,5539 h60
  text "REGISTRATION TOLERANCES:" at 11407.23,5534 h60
  text "METAL" at 12607,5534 h60
  text "5" at 13183.2,5534 h60
  text "3" at 14016.2,5534 h60
  text "MIL" at 14132.46,5534 h60
  text "MATERIAL:" at 11332.46,5324.54 h60
  text "FR-4 High Tg" at 12318.9,5184.21 h60
  text "X" at 11606.46,5175.64 h60
  text "FR-408" at 11753.46,5175.64 h60
  text "OTHER" at 13241.46,5175.64 h60
  text "63 MIL (1.6mm) +/-10%" at 12073.56,5012.92 h60
  text "THICKNESS:" at 11407.23,5008.64 h60
  text "X" at 11945.4,5008.64 h60
  text "OTHER" at 13358.46,5008.64 h60
  text "TOLERANCE:" at 11407.23,4850.64 h60
  text "X" at 12246.53,4850.64 h60
  text "ANSI IPC-6012 TYPE 3 CLASS 2" at 12433.48,4850.64 h60
  text "OTHER +/-" at 12433.46,4694.64 h60
  text "BOW & TWIST:" at 11407.23,4537.64 h60
  text "X" at 12246.53,4537.64 h60
  text "ANSI IPC-6012 TYPE 3 CLASS 2" at 12433.48,4537.64 h60
  text "OTHER +/-" at 12433.46,4379.13 h60
  text "COPPER THICKNESS (FINISHED):" at 11332.46,4243.64 h60
  text "1.4MIL (1oz)" at 12212.46,4090.92 h60
  text "2MIL (1.4oz)" at 12979.46,4090.92 h60
  text "2.8MIL (2oz)" at 13706.46,4090.92 h60
  text "OUTER:" at 11689.46,4086.64 h60
  text "X" at 12084,4086 h60
  text "1.4MIL (1oz)" at 12212.46,3933.92 h60
  text "2.8MIL (2oz)" at 12979.46,3933.92 h60
  text "N/A" at 13706,3934.29 h60
  text "INNER SIGNAL:" at 11400.38,3929.64 h60
  text "X" at 12085.42,3929.64 h60
  text "DRILLING:" at 11332.46,3790.64 h60
  text "REFERENCE:" at 11407.23,3673.64 h60
  text "X" at 12055.46,3673.64 h60
  text "AS SHOWN" at 12242.46,3673.64 h60
  text "X" at 12956.46,3673.64 h60
  text "NC_DRILL FILES" at 13093.46,3673.64 h60
  text "PTH MIN COPPER THICKNESS:" at 11407.23,3515.64 h60
  text "X" at 12757.46,3515.64 h60
  text "1MIL" at 12894.46,3515.64 h60
  text "OTHER" at 13391.46,3515.64 h60
  text "BOARD FINISH:" at 11332.46,3356.64 h60
  text "SILKSCREEN:" at 11487.68,3238.64 h60
  text "X" at 12436.46,3238.64 h60
  text "TOP" at 12562.46,3238.64 h60
  text "X" at 12946.46,3238.64 h60
  text "BOTTOM" at 13073.46,3238.64 h60
  text "SILKSCREEN COLOR:" at 11486.01,3072.64 h60
  text "X" at 12433.75,3072.64 h60
  text "WHITE" at 12560.79,3072.64 h60
  text "OTHER" at 13071.79,3072.64 h60
  text "SOLDER RESIST COLOR:" at 11592.01,2921.64 h60
  text "GREEN" at 12286.79,2762.44 h60
  text "X" at 12049,2750 h60
  text "BLUE" at 12857,2744 h60
  text "OTHER" at 13306,2740 h60
  text "IMMERSION GOLD (ENIG)" at 12393.46,2553.92 h60
  text "ENEPIG" at 13731,2550.64 h60
  text "SURFACE FINISH:" at 11332.46,2549.64 h60
  text "X" at 12206.51,2549.64 h60
  text "IMM. TIN/SILVER OR EQUIV" at 11662,2392.64 h60
  text "OTHER" at 13093.46,2392.64 h60
  text "ARRAY/PANEL:" at 11332.46,2213.64 h60
  text "CUT AND TRIM PER MECH LAYER 1" at 12393.46,2209.35 h60
  text "N.C. ROUTE" at 12393.46,2057.64 h60
  text "X" at 13072.46,2057.64 h60
  text "V. SCORE" at 13259.46,2057.64 h60
  text "CERTIFICATION:" at 11332.46,1920.64 h60
  text "MATERIALS AND WORKMANSHIP FOR ALL PCBS" at 12057.46,1920.64 h60
  text "TO MEET OR EXCEED THE REQUIREMENTS OF:" at 12057.46,1822.64 h60
  text "X" at 11683.96,1686.13 h60
  text "ANSI IPC-A-600F CLASS ->" at 11822.96,1686.13 h60
  text "X" at 13462.02,1686.13 h60
  text "2" at 13580.96,1686.14 h60
  text "1" at 13265.96,1684.64 h60
  text "3" at 13934.96,1684.64 h60
  text "X" at 11686.02,1526.64 h60
  text "UL 94V-0" at 11822.96,1526.64 h60
  text "X" at 12498.02,1526.64 h60
  text "RoHS" at 12634.96,1526.64 h60
  text "OTHER" at 13279.36,1526.64 h60
  text "PER ORDER" at 13676.42,1526.64 h60
  text "ADDITIONAL REQUIREMENTS:" at 11332.46,1385.64 h60
  text "VIA TENTING:" at 12807,1292.36 h60
  text "X" at 13595.29,1292.48 h60
  text "YES" at 13378.67,1283.28 h60
  text "NO" at 13773.47,1283.05 h60
  text "MICROSECTION:" at 11407.23,1270.64 h60
  text "YES" at 12312.96,1270.64 h60
  text "REQUIRED" at 13174.46,1114.49 h60
  text "BARE BOARD ELEC. TEST:" at 11407.23,1111.64 h60
  text "NONE" at 12712.96,1111.64 h60
  text "X" at 13047.46,1111.64 h60
  text "PER ORDER" at 13766.46,1111.64 h60
  text "MANUFACTURER'S UL:" at 11407.23,954.64 h60
  text "RAIL" at 12572.96,950.35 h60
  text "METAL" at 13064.77,950.35 h60
  text "X" at 13440,950 h60
  text "SILK" at 13576.46,950.35 h60
M11 Gerber Information:
  lines w10: -292,-930.17 6308,-930.17 ; -292,-726.83 6310,-726.83 ; -292,-523.5 -292,-1133.5 3713,-1133.5 6310,-1133.5 6310,-523.5 -291.5,-523.5 -291.5,-1133.5 1284,-1133.5 ; 2173,-1133.5 2173,-523.5 ; 3690,-730 3690,-526.67 ; 4280,-726.83 4280,-523.5 ; 4902,-1140 4902,-937.17
  text "ALL ARTWORK VIEWED FROM TOP SIDE" at -228.5,-655.67 h60
  text "BOARD #:" at 2248,-655.67 h60
  text "SVN REV:" at 4476,-655.67 h60
  text ".VersionControl_RevNumber" at 4982,-655.67 h60
  text "REV: E1" at 3785,-657 h60
  text "ISE-PLC-AIM-300" at 2720,-660 h60
  text "LAYER NAME =" at -228.5,-858.49 h60
  text "PLOT NAME =" at -228.5,-1064.34 h60
  text ".plot_File_Name" at 577,-1064.34 h60
  text "GENERATED    :" at 2250,-1064.34 h60
  text ".Print_Date" at 3119.5,-1064.34 h60
  text ".Print_Time" at 3848.5,-1064.34 h60
  text "TEXAS INSTRUMENTS" at 5113,-1064.34 h60
M12 Stackup:
  lines w6: 11304,7657.5 14205,7657.5 ; 11304,7766 14205,7766 ; 11244,6974 ccw(c11279,6974) 11279,6939 14230,6939 ccw(c14230,6974) 14265,6974 14265,7858 ccw(c14230,7858) 14230,7893 11279,7893 ccw(c11279,7858) 11244,7858 11244,6974
  text "Layer Stack Up Detail for: TIDA-00170.PcbDoc" at 11304,7794.1 h48
  text "Layer" at 11304,7725.5 h25
  text "Gerber" at 12317.81,7725.5 h25
  text "Copper" at 12992.59,7725.5 h25
  text "Dielectric" at 13708.19,7725.5 h25
  text "Name" at 11304,7675.5 h25
  text "Document" at 12317.81,7675.5 h25
  text "Thickness" at 12992.59,7675.5 h25
  text "Material" at 13708.19,7675.5 h25
  text "Top Solder Mask" at 11304,7604.81 h35
  text "(.GTS)" at 12317.81,7604.81 h35
  text "Solder Resist" at 13708.19,7604.81 h35
  text "Top Layer" at 11304,7505.44 h35
  text "(.GTL)" at 12317.81,7505.44 h35
  text "1.4mil" at 12992.59,7505.44 h35
  text "FR-4" at 13708.19,7455.75 h35
  text "L2_GND-PLANE" at 11304,7406.06 h35
  text "(.G1)" at 12317.81,7406.06 h35
  text "1.4mil" at 12992.59,7406.06 h35
  text "FR-4" at 13708.19,7356.38 h35
  text "L3_PWR-PLANE" at 11304,7306.69 h35
  text "(.G2)" at 12317.81,7306.69 h35
  text "1.4mil" at 12992.59,7306.69 h35
  text "FR-4" at 13708.19,7257 h35
  text "Bottom Layer" at 11304,7207.31 h35
  text "(.GBL)" at 12317.81,7207.31 h35
  text "1.4mil" at 12992.59,7207.31 h35
  text "Bottom Solder Mask" at 11304,7107.94 h35
  text "(.GBS)" at 12317.81,7107.94 h35
  text "Solder Resist" at 13708.19,7107.94 h35
M13 Component Bodies Top:
  text ".Layer_Name" at 577,-858.49 h60
M14 Component Bodies Bottom:
  text ".Layer_Name" at 577,-858.49 h60
M15 Courtyards Top:
  text ".Layer_Name" at 577,-858.49 h60
M16 Courtyards Bottom:
  text ".Layer_Name" at 577,-858.49 h60
Drill Drawing:
  text ".legend" at 4281.25,609.45 h60
  text "Drill Table" at 4280,455 h60
  text "FOR 8MIL DRILL +0/-8MIL" at 4340,320 h60
  text "FOR 12MIL DRILL +0/-12MIL" at 4342.7,214.2 h60
  text "FOR 16MIL DRILL +0/-16MIL" at 4340,100 h60
  text ".Layer_Name" at 577,-858.49 h60

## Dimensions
0,2000 to 3780,2000 on Drill Drawing
3780,2000 to 3780,0 on Drill Drawing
